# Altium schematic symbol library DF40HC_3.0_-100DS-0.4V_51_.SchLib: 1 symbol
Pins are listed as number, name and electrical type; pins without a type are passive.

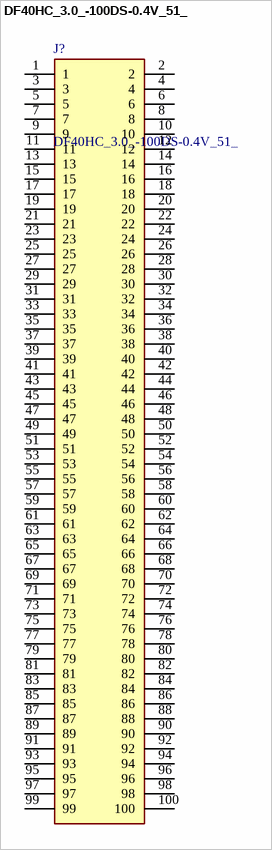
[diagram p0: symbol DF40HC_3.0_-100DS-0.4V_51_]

## DF40HC_3.0_-100DS-0.4V_51_
designator J?
Mezzanine Connectors (Board to Board) SMD,P=0.4mm RoHS; Manufacturer_Name: Hirose; Manufacturer_Part_Number: DF40HC(3.0)-100DS-0.4V(51); Geometry.Height: 3.05mm
footprint DF40HC30100DS04V51
pins: 1, 2, 3, 4, 5, 6, 7, 8, 9, 10, 11, 12, 13, 14, 15, 16, 17, 18, 19, 20, 21, 22, 23, 24, 25, 26, 27, 28, 29, 30, 31, 32, 33, 34, 35, 36, 37, 38, 39, 40, 41, 42, 43, 44, 45, 46, 47, 48, 49, 50, 51, 52, 53, 54, 55, 56, 57, 58, 59, 60, 61, 62, 63, 64, 65, 66, 67, 68, 69, 70, 71, 72, 73, 74, 75, 76, 77, 78, 79, 80, 81, 82, 83, 84, 85, 86, 87, 88, 89, 90, 91, 92, 93, 94, 95, 96, 97, 98, 99, 100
